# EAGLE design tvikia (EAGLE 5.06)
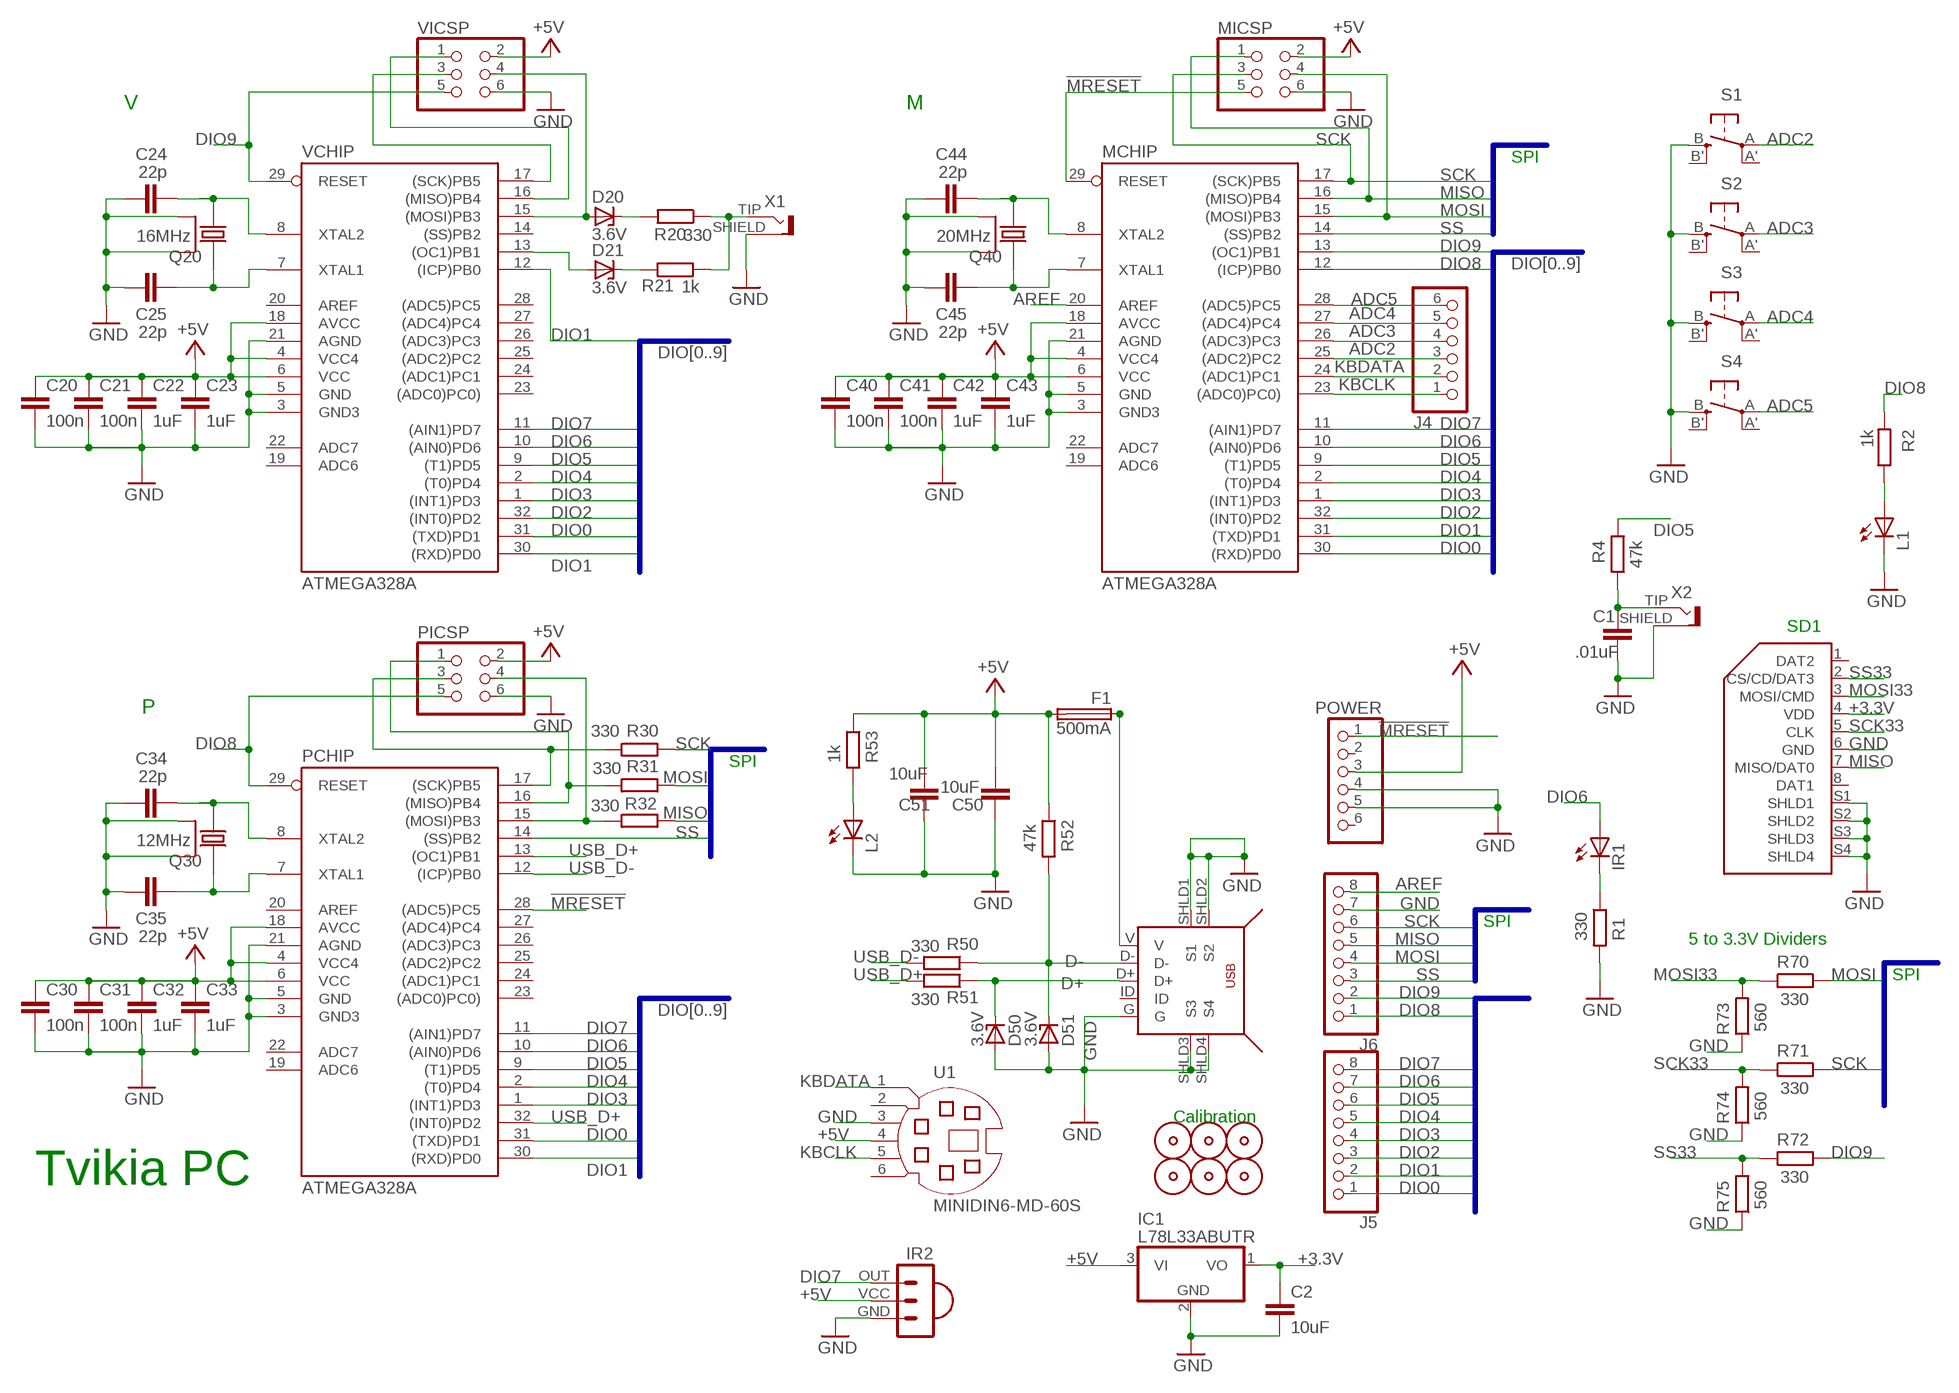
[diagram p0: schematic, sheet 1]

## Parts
C1  .01uF  C-EUC0603  [C0603]
C2  10uF  C-EUC0603  [C0603]
C20  100n  C-EUC0603  [C0603]
C21  100n  C-EUC0603  [C0603]
C22  1uF  C-EUC0603  [C0603]
C23  1uF  C-EUC0603  [C0603]
C24  22p  C-EUC0603  [C0603]
C25  22p  C-EUC0603  [C0603]
C30  100n  C-EUC0603  [C0603]
C31  100n  C-EUC0603  [C0603]
C32  1uF  C-EUC0603  [C0603]
C33  1uF  C-EUC0603  [C0603]
C34  22p  C-EUC0603  [C0603]
C35  22p  C-EUC0603  [C0603]
C40  100n  C-EUC0603  [C0603]
C41  100n  C-EUC0603  [C0603]
C42  1uF  C-EUC0603  [C0603]
C43  1uF  C-EUC0603  [C0603]
C44  22p  C-EUC0603  [C0603]
C45  22p  C-EUC0603  [C0603]
C50  10uF  C-EUC0603  [C0603]
C51  10uF  C-EUC0603  [C0603]
D20  3.6V  ZENER-DIODESOT23  [SOT23]
D21  3.6V  ZENER-DIODESOT23  [SOT23]
D50  3.6V  ZENER-DIODESOT23  [SOT23]
D51  3.6V  ZENER-DIODESOT23  [SOT23]
F1  500mA  FUSE0402  [0402]
IC1  L78L33ABUTR  [SOT89]
IR1  LED5MM  [LED5MM]
IR2  IR-RECV-TSOP323  [IR-RECV-TSOP323]
J4  PINHD-1X6-CIRC  [1X06]
J5  PINHD-1X8-CIRC  [1X08]
J6  PINHD-1X8-CIRC  [1X08]
L1  LEDCHIP-LED0603  [CHIP-LED0603]
L2  LEDCHIPLED_0603  [CHIPLED_0603]
MCHIP  ATMEGA328A  [TQFP32-08]
MICSP  PINHD-2X3  [2X03]
PCHIP  ATMEGA328A  [TQFP32-08]
PICSP  PINHD-2X3  [2X03]
POWER  PINHD-1X6-CIRC  [1X06]
Q20  16MHz  NX3225SA  [NX3225SA]
Q30  12MHz  NX3225SA  [NX3225SA]
Q40  20MHz  NX3225SA  [NX3225SA]
R1  330  R-EU_R0603  [R0603]
R2  1k  R-EU_R0603  [R0603]
R4  47k  R-EU_R0603  [R0603]
R20  330  R-EU_R0603  [R0603]
R21  1k  R-EU_R0603  [R0603]
R30  330  R-EU_R0603  [R0603]
R31  330  R-EU_R0603  [R0603]
R32  330  R-EU_R0603  [R0603]
R50  330  R-EU_R0603  [R0603]
R51  330  R-EU_R0603  [R0603]
R52  47k  R-EU_R0603  [R0603]
R53  1k  R-EU_R0603  [R0603]
R70  330  R-EU_R0603  [R0603]
R71  330  R-EU_R0603  [R0603]
R72  330  R-EU_R0603  [R0603]
R73  560  R-EU_R0603  [R0603]
R74  560  R-EU_R0603  [R0603]
R75  560  R-EU_R0603  [R0603]
S1  EVQ-Q2P02W  [EVQ-Q2P02W]
S2  EVQ-Q2P02W  [EVQ-Q2P02W]
S3  EVQ-Q2P02W  [EVQ-Q2P02W]
S4  EVQ-Q2P02W  [EVQ-Q2P02W]
SD1  MICROSD_3M_2900  [MICROSD_3M_2900]
U1  MINIDIN6-MD-60S  [MINIDIN6-MD-60S]
U$1  CALIBRATION-MARK  [CALIBRATION-MARK]
U$4  CALIBRATION-MARK  [CALIBRATION-MARK]
U$5  CALIBRATION-MARK  [CALIBRATION-MARK]
U$6  CALIBRATION-MARK  [CALIBRATION-MARK]
U$8  MICROUSB-ZX62-B-5PA  [MICROUSB-ZX62-B-5PA]
U$10  CALIBRATION-MARK  [CALIBRATION-MARK]
U$12  CALIBRATION-MARK  [CALIBRATION-MARK]
VCHIP  ATMEGA328A  [TQFP32-08]
VICSP  PINHD-2X3  [2X03]
X1  RCA-KOBICONN-161-03XX-E  [RCA-161-03XX-E]
X2  RCA-KOBICONN-161-03XX-E  [RCA-161-03XX-E]

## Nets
!MRESET: MCHIP.29(RESET) MICSP.5 PCHIP.28((ADC5)PC5) POWER.1
+3.3V: C2.1 IC1.1(VO) SD1.4(VDD)
+5V: C20.1 C21.1 C22.1 C23.1 C30.1 C31.1 C32.1 C33.1 C40.1 C41.1 C42.1 C43.1 C50.1 C51.1 F1.2 IC1.3(VI) IR2.VCC MCHIP.4(VCC4) MCHIP.6(VCC) MCHIP.18(AVCC) MICSP.2 PCHIP.4(VCC4) PCHIP.6(VCC) PCHIP.18(AVCC) PICSP.2 POWER.3 R52.1 R53.1 U1.4 VCHIP.4(VCC4) VCHIP.6(VCC) VCHIP.18(AVCC) VICSP.2
ADC2: J4.3 MCHIP.25((ADC2)PC2) S1.A(P)
ADC3: J4.4 MCHIP.26((ADC3)PC3) S2.A(P)
ADC4: J4.5 MCHIP.27((ADC4)PC4) S3.A(P)
ADC5: J4.6 MCHIP.28((ADC5)PC5) S4.A(P)
AREF: J6.8 MCHIP.20(AREF)
D+: D50.3(C) R51.1 U$8.D+
D-: D51.3(C) R50.1 R52.2 U$8.D-
DIO0: J5.1 MCHIP.30((RXD)PD0) PCHIP.31((TXD)PD1) VCHIP.31((TXD)PD1)
DIO1: J5.2 MCHIP.31((TXD)PD1) PCHIP.30((RXD)PD0) VCHIP.12((ICP)PB0) VCHIP.30((RXD)PD0)
DIO2: J5.3 MCHIP.32((INT0)PD2) VCHIP.32((INT0)PD2)
DIO3: J5.4 MCHIP.1((INT1)PD3) PCHIP.1((INT1)PD3) VCHIP.1((INT1)PD3)
DIO4: J5.5 MCHIP.2((T0)PD4) PCHIP.2((T0)PD4) VCHIP.2((T0)PD4)
DIO5: J5.6 MCHIP.9((T1)PD5) PCHIP.9((T1)PD5) R4.2 VCHIP.9((T1)PD5)
DIO6: IR1.A J5.7 MCHIP.10((AIN0)PD6) PCHIP.10((AIN0)PD6) VCHIP.10((AIN0)PD6)
DIO7: IR2.OUT J5.8 MCHIP.11((AIN1)PD7) PCHIP.11((AIN1)PD7) VCHIP.11((AIN1)PD7)
DIO8: J6.1 MCHIP.12((ICP)PB0) PCHIP.29(RESET) PICSP.5 R2.2
DIO9: J6.2 MCHIP.13((OC1)PB1) R72.2 VCHIP.29(RESET) VICSP.5
GND [power]: C1.2 C2.2 C20.2 C21.2 C22.2 C23.2 C24.1 C25.1 C30.2 C31.2 C32.2 C33.2 C34.1 C35.1 C40.2 C41.2 C42.2 C43.2 C44.1 C45.1 C50.2 C51.2 D50.1(A) D51.1(A) IC1.2(GND) IR2.GND J6.7 L1.C L2.C MCHIP.3(GND3) MCHIP.5(GND) MCHIP.21(AGND) MICSP.6 PCHIP.3(GND3) PCHIP.5(GND) PCHIP.21(AGND) PICSP.6 POWER.4 POWER.5 Q20.2(GND2) Q20.4(GND) Q30.2(GND2) Q30.4(GND) Q40.2(GND2) Q40.4(GND) R1.2 R73.1 R74.1 R75.1 S1.B(S) S2.B(S) S3.B(S) S4.B(S) SD1.6(GND) SD1.S1(SHLD1) SD1.S2(SHLD2) SD1.S3(SHLD3) SD1.S4(SHLD4) U1.3 U$8.G U$8.SHLD1(S1) U$8.SHLD2(S2) U$8.SHLD3(S3) U$8.SHLD4(S4) VCHIP.3(GND3) VCHIP.5(GND) VCHIP.21(AGND) VICSP.6 X1.SHIELD X2.SHIELD
KBCLK: J4.1 MCHIP.23((ADC0)PC0)) U1.5
KBDATA: J4.2 MCHIP.24((ADC1)PC1) U1.1
MISO: J6.5 MCHIP.16((MISO)PB4) MICSP.1 R32.1 SD1.7(MISO/DAT0)
MOSI: J6.4 MCHIP.15((MOSI)PB3) MICSP.4 R31.1 R70.2
MOSI33: R70.1 R73.2 SD1.3(MOSI/CMD)
N$2: IR1.K(C) R1.1
N$3: L2.A R53.2
N$4: C34.2 PCHIP.8(XTAL2) Q30.1
N$5: C1.1 R4.1 X2.TIP
N$8: F1.1 U$8.V
N$9: VCHIP.16((MISO)PB4) VICSP.1
N$10: C24.2 Q20.1 VCHIP.8(XTAL2)
N$11: C25.2 Q20.3 VCHIP.7(XTAL1)
N$12: D20.3(C) R20.2
N$13: D21.1(A) VCHIP.13((OC1)PB1)
N$14: D21.3(C) R21.1
N$15: R20.1 R21.2 X1.TIP
N$23: C35.2 PCHIP.7(XTAL1) Q30.3
N$24: VCHIP.17((SCK)PB5) VICSP.3
N$28: C44.2 MCHIP.8(XTAL2) Q40.1
N$29: C45.2 MCHIP.7(XTAL1) Q40.3
N$37: L1.A R2.1
PIXEL1: D20.1(A) VCHIP.15((MOSI)PB3) VICSP.4
PMISO: PCHIP.15((MOSI)PB3) PICSP.4 R32.2
PMOSI: PCHIP.16((MISO)PB4) PICSP.1 R31.2
PSCK: PCHIP.17((SCK)PB5) PICSP.3 R30.2
SCK: J6.6 MCHIP.17((SCK)PB5) MICSP.3 R30.1 R71.2
SCK33: R71.1 R74.2 SD1.5(CLK)
SS: J6.3 MCHIP.14((SS)PB2) PCHIP.14((SS)PB2)
SS33: R72.1 R75.2 SD1.2(CS/CD/DAT3)
USB_D+: PCHIP.13((OC1)PB1) PCHIP.32((INT0)PD2) R51.2
USB_D-: PCHIP.12((ICP)PB0) R50.2
Unconnected: MCHIP.19(ADC6) MCHIP.22(ADC7) PCHIP.19(ADC6) PCHIP.20(AREF) PCHIP.22(ADC7) PCHIP.23((ADC0)PC0)) PCHIP.24((ADC1)PC1) PCHIP.25((ADC2)PC2) PCHIP.26((ADC3)PC3) PCHIP.27((ADC4)PC4) POWER.2 POWER.6 S1.A'(P1) S1.B'(S1) S2.A'(P1) S2.B'(S1) S3.A'(P1) S3.B'(S1) S4.A'(P1) S4.B'(S1) SD1.1(DAT2) SD1.8(DAT1) U1.2 U1.6 U$8.ID VCHIP.14((SS)PB2) VCHIP.19(ADC6) VCHIP.20(AREF) VCHIP.22(ADC7) VCHIP.23((ADC0)PC0)) VCHIP.24((ADC1)PC1) VCHIP.25((ADC2)PC2) VCHIP.26((ADC3)PC3) VCHIP.27((ADC4)PC4) VCHIP.28((ADC5)PC5)

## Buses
DIO[0..9]
SPI:SCK,MOSI,MISO,SS

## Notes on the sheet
- V | M
- SPI
- SD1
- P
- SPI
- SPI
- 5 to 3.3V Dividers
- SPI
- Calibration
- Tvikia PC

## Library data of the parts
C1 C2 C20-C25 C30-C35 C40-C45 C50 C51 = rcl:C-EU: CAPACITOR, European symbol
D20 D21 D50 D51 = diode:ZENER-DIODE: Z-Diode
F1 = tvikia:FUSE0402
IC1 = tvikia:L78L33ABUTR: 250 mA, 16V, Low Quiescent Current LDO Regulator Source: http://ww1.microchip.com/downloads/en/DeviceDoc/22049b.pdf
IR1 L1 L2 = led:LED: LED
IR2 = tvikia:IR-RECV-TSOP323
J4 POWER = tvikia:PINHD-1X6-CIRC: PIN HEADER
J5 J6 = tvikia:PINHD-1X8-CIRC: PIN HEADER
MCHIP PCHIP VCHIP = tvikia:ATMEGA328: MICROCONTROLLER 4 Kbytes FLASH 128 bytes SRAM 256 bytes EEPROM UART 6-channel 10 bit ADC
MICSP PICSP VICSP = pinhead:PINHD-2X3: PIN HEADER
Q20 Q30 Q40 = tvikia:NX3225SA
R1 R2 R4 R20 R21 R30-R32 R50-R53 R70-R75 = rcl:R-EU_: RESISTOR, European symbol
S1-S4 = tvikia:EVQ-Q2P02W
SD1 = tvikia:MICROSD_3M_2900
U1 = tvikia:MINIDIN6-MD-60S
U$1 U$4-U$6 U$10 U$12 = tvikia:CALIBRATION-MARK: Calibration mark for board pick-n-place.
U$8 = tvikia:MICROUSB-ZX62-B-5PA
X1 X2 = tvikia:RCA-KOBICONN-161-03XX-E

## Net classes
0 default: width 0.203 mm, drill 0.305 mm, clearance 0.203 mm
1 power: width 0.356 mm, drill 0.305 mm, clearance 0.203 mm
2 gnd: width 0.356 mm, drill 0.305 mm, clearance 0.203 mm

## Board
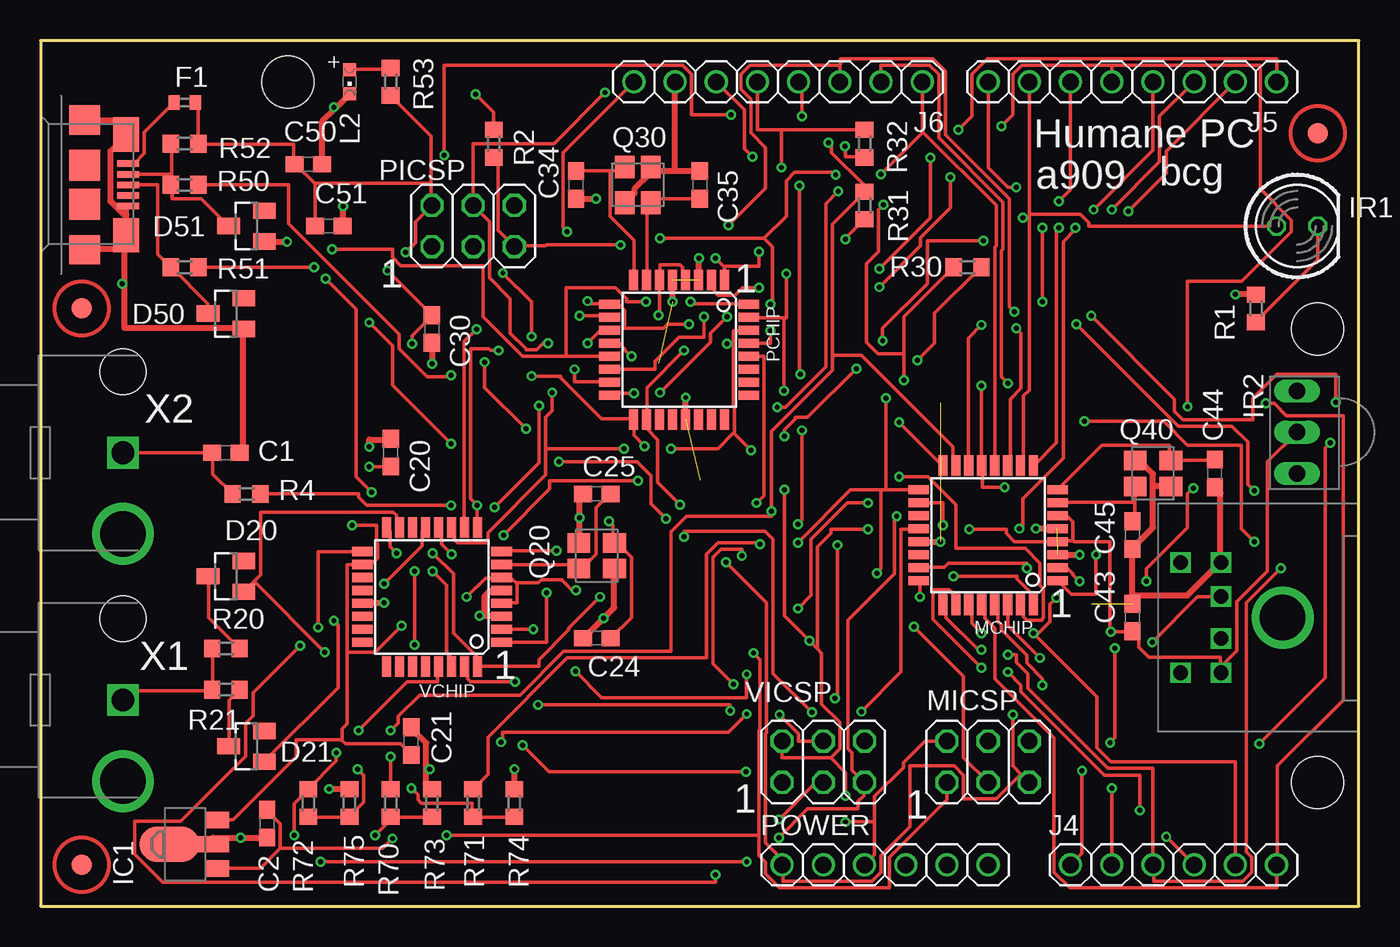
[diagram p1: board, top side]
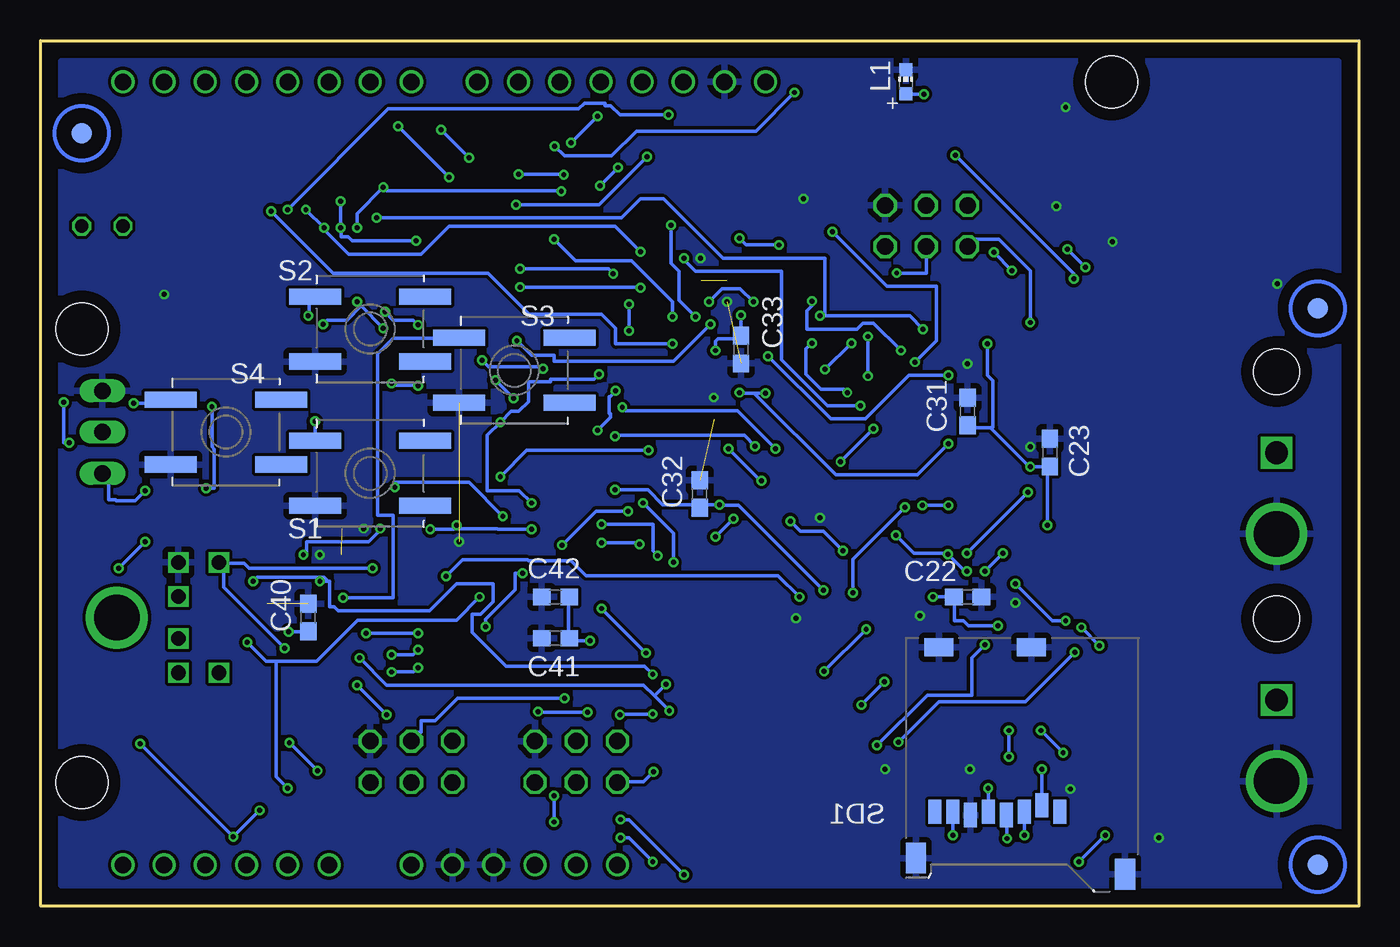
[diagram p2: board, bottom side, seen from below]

Size 81.28 x 53.34 mm. Coordinates in mm from the lower left corner, seen from the top.
Outline: 0,0 81.28,0 81.28,53.34 0,53.34 0,0
Copper layers (1*16): Top 0.035mm / dielectric 1.5mm / Bottom 0.035mm
Design rules "chung_nam_design_rules *": minimum track width 8mil, minimum drill 12mil, track to track 8mil, track to pad 8mil, pad to pad 5mil, via to via 15mil, smd to smd 5mil, copper to edge 30mil, drill to drill 30mil, minimum pad ring 7mil, minimum via ring 6mil, stop-mask expansion 3mil, vias tented up to drill 0mil, thermal gap 14mil
Holes 3.2 mm at 15.24,50.8 78.74,35.56 78.74,7.62

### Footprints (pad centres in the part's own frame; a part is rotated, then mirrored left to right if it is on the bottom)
C0603 = smd 1.1 x 1: 1 -0.85,0; 2 0.85,0
SOT23 = smd 1 x 1.4: 1 -0.95,-1.1; 2 0.95,-1.1; 3 0,1.1
0402 = smd 0.7 x 0.9: 1 -0.65,0; 2 0.65,0
SOT89 = smd 1 x 1.5: 1 -1.499,-1.981; 3 1.499,-1.981 | smd 1 x 2: 2 0,-1.727 | smd 2.2 x 3.7: 2@1 0,0.94
LED5MM = drill 0.813 octagon: A -1.27,0; K 1.27,0
IR-RECV-TSOP323 = drill 1.016 long: GND -2.54,0; OUT 2.54,0; VCC 0,0
1X06 = drill 1.016 round: 1 -6.35,0; 2 -3.81,0; 3 -1.27,0; 4 1.27,0; 5 3.81,0; 6 6.35,0
1X08 = drill 1.016 round: 1 -8.89,0; 2 -6.35,0; 3 -3.81,0; 4 -1.27,0; 5 1.27,0; 6 3.81,0; 7 6.35,0; 8 8.89,0
CHIP-LED0603 = smd 0.8 x 0.8: A 0,-0.75; C 0,0.75
CHIPLED_0603 = smd 0.8 x 0.8: A 0,-0.75; C 0,0.75
TQFP32-08 = smd 1.27 x 0.559: 1 -4.293,2.8; 2 -4.293,2; 3 -4.293,1.2; 4 -4.293,0.4; 5 -4.293,-0.4; 6 -4.293,-1.2; 7 -4.293,-2; 8 -4.293,-2.8; 17 4.293,-2.8; 18 4.293,-2; 19 4.293,-1.2; 20 4.293,-0.4; 21 4.293,0.4; 22 4.293,1.2; 23 4.293,2; 24 4.293,2.8 | smd 0.559 x 1.27: 9 -2.8,-4.293; 10 -2,-4.293; 11 -1.2,-4.293; 12 -0.4,-4.293; 13 0.4,-4.293; 14 1.2,-4.293; 15 2,-4.293; 16 2.8,-4.293; 25 2.8,4.293; 26 2,4.293; 27 1.2,4.293; 28 0.4,4.293; 29 -0.4,4.293; 30 -1.2,4.293; 31 -2,4.293; 32 -2.8,4.293
2X03 = drill 1.016 octagon: 1 -2.54,-1.27; 2 -2.54,1.27; 3 0,-1.27; 4 0,1.27; 5 2.54,-1.27; 6 2.54,1.27
NX3225SA = smd 1.4 x 1.2: 1 -1.1,-0.8; 2 1.1,-0.8; 3 1.1,0.8; 4 -1.1,0.8
R0603 = smd 1 x 1.1: 1 -0.85,0; 2 0.85,0
EVQ-Q2P02W = smd 3.2 x 1: A -3.4,2; A' 3.4,2; B -3.4,-2; B' 3.4,-2
MICROSD_3M_2900 = smd 0.8 x 1.5: 1 -9.5,10.7; 2 -8.4,10.3; 3 -7.3,10.7; 4 -6.2,10.9; 5 -5.1,10.7; 6 -4,10.9; 7 -2.9,10.7; 8 -1.8,10.7 | smd 1.24 x 1.9: S1 -13.52,14.55; S2 -0.62,13.55 | smd 1.8 x 1.1: S3 -7.75,0.55; S4 -2.05,0.55
MINIDIN6-MD-60S = drill 0.9 square: 1 -1.3,-8.5; 2 1.3,-8.5; 3 -3.4,-8.5; 4 3.4,-8.5; 5 -3.4,-11; 6 3.4,-11 | drill 2.8 round: P$7 0,-4.7
CALIBRATION-MARK = smd 1.27 x 1.27: P$1 0,0
MICROUSB-ZX62-B-5PA = smd 0.4 x 1.35: D+ 0,4.13; D- -0.65,4.13; G 1.3,4.13; ID 0.65,4.13; V -1.3,4.13 | smd 1.9 x 1.9: P$8 1.2,1.45; P$9 -1.2,1.45 | smd 2.1 x 1.6: SHLD1 -3.1,4; SHLD2 3.1,4 | smd 1.8 x 1.9: SHLD3 -4,1.45; SHLD4 4,1.45
RCA-161-03XX-E = drill 2.8 round: SHIELD 5,0 | drill 1.4 square: TIP 0,0 | hole 2.8: -5,0

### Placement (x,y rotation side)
C1  11.43,27.94 0 top
C2  13.97,5.08 270 top
C20  21.59,27.94 90 top
C21  22.86,10.16 90 top
C22  24.13,19.05 0 bottom
C23  19.05,27.94 90 bottom
C24  34.29,16.51 0 top
C25  34.29,25.4 0 top
C30  24.13,35.56 270 top
C31  24.13,30.48 90 bottom
C32  40.64,25.4 90 bottom
C33  38.1,34.29 270 bottom
C34  33.02,44.45 90 top
C35  40.64,44.45 270 top
C40  64.77,17.78 90 bottom
C41  49.53,16.51 180 bottom
C42  49.53,19.05 180 bottom
C43  67.31,17.78 90 top
C44  72.39,26.67 90 top
C45  67.31,22.86 90 top
C50  16.51,45.72 0 top
C51  17.78,41.91 0 top
D20  11.43,20.32 90 top
D21  12.7,9.84 90 top
D50  11.43,36.51 90 top
D51  12.7,41.91 90 top
F1  8.89,49.53 0 top
IC1  8.89,3.81 90 top
IR1  77.47,41.91 0 top
IR2  77.47,29.21 270 top
J4  69.85,2.54 0 top
J5  67.31,50.8 180 top
J6  45.47,50.8 180 top
L1  27.94,50.8 0 bottom
L2  19.05,50.8 180 top
MCHIP  58.42,22.86 180 top
MICSP  58.42,8.89 0 top
PCHIP  39.37,34.29 270 top
PICSP  26.67,41.91 0 top
POWER  52.07,2.54 0 top
Q20  34.29,21.59 180 top
Q30  36.83,44.45 270 top
Q40  68.58,26.67 180 top
R1  74.93,36.83 90 top
R2  27.94,46.99 270 top
R4  12.7,25.4 0 top
R20  11.43,15.88 0 top
R21  11.43,13.34 180 top
R30  57.15,39.37 0 top
R31  50.8,43.18 270 top
R32  50.8,46.99 270 top
R50  8.89,44.45 0 top
R51  8.89,39.37 0 top
R52  8.89,46.99 180 top
R53  21.59,50.8 90 top
R70  21.59,6.35 90 top
R71  26.67,6.35 90 top
R72  16.51,6.35 90 top
R73  24.13,6.35 270 top
R74  29.21,6.35 270 top
R75  19.05,6.35 270 top
S1  60.96,26.67 0 bottom
S2  60.96,35.56 0 bottom
S3  52.07,33.02 0 bottom
S4  69.85,29.21 0 bottom
SD1  27.94,16.51 180 bottom
U1  81.28,17.78 270 top
U$1  78.74,47.62 0 bottom
U$4  2.54,2.54 0 top
U$5  78.74,47.62 0 top
U$6  2.54,36.83 0 top
U$8  1.27,44.45 270 top
U$10  2.54,2.54 0 bottom
U$12  2.54,36.83 0 bottom
VCHIP  24.13,19.05 180 top
VICSP  48.26,8.89 0 top
X1  5.08,12.7 270 top
X2  5.08,27.94 270 top

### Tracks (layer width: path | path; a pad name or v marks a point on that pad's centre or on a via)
!MRESET  (via drill 0.3)
  Top 0.203: v61.77,13.61 61.77,14.02 60.81,14.99 60.81,15.44 59.23,17.02 59.23,17.32 59.03,17.53 59.03,18.34 58.83,18.54 MCHIP.29 | v59.94,11.79 59.94,8.64 60.45,8.13 | 60.45,8.13 MICSP.5 | v44.15,24.84 44.6,25.3 44.6,33.88 43.69,33.88 PCHIP.28 | v42.27,21.18 44.76,18.69 44.76,10.67 44.7,10.62 44.7,3.91 45.72,2.9 POWER.1 45.77,2.49 45.77,1.52 51.26,1.52 51.82,2.08 51.82,3.1 53.59,4.88 53.59,8.64 56.34,8.64 56.9,8.08 56.9,6.6 58.93,6.6 60.45,8.13
  Bottom 0.203: v59.94,11.79 v61.77,13.61 | v44.15,24.84 42.27,22.96 v42.27,21.18
+3.3V  (via drill 0.3)
  Top 0.203: 14.78,3.56 14.78,5.08 13.97,5.89 C2.1 | 14.78,3.56 13.56,2.34 10.87,2.34 IC1.1 | v21.69,4.17 21.08,3.56 14.78,3.56
  Bottom 0.203: v21.69,4.17 21.69,5.59 SD1.4
+5V  (via drill 0.3)
  Top 0.203: F1.2 9.7,49.38 9.7,46.99 R52.1 9.8,46.94 15.6,46.94 15.6,45.77 C50.1 15.7,45.72 16.92,44.5 | 16.92,44.5 16.92,41.91 C51.1 | v21.39,39.17 24.13,36.42 C30.1 24.08,36.32 22.91,35.15 v22.91,34.65 | v22.5,40.28 23.11,40.89 23.11,42.16 PICSP.2 24.08,43.23 24.08,44.55 | 24.08,44.55 24.08,47.45 21.59,49.94 R53.1 | 16.92,44.5 16.97,44.55 24.08,44.55 | v20.27,27.08 21.59,27.08 C20.1 | v26.26,19.05 27.43,20.22 28.4,20.22 VCHIP.6 28.5,20.22 29.01,20.22 29.36,19.86 | 29.36,19.86 29.36,18.69 28.45,18.69 VCHIP.4 | 18.54,10.26 18.8,10.01 22.2,10.01 22.86,9.35 C21.1 | 18.54,10.26 15.75,10.26 15.75,9.2 11.89,5.33 10.87,5.33 IC1.3 | 18.9,15.65 18.9,11.23 18.59,10.92 18.59,10.31 18.54,10.26 | 18.9,15.65 18.9,21.03 19.81,21.03 VCHIP.18 19.91,21.08 20.42,21.08 20.78,21.44 20.78,22.3 20.73,22.35 20.73,23.47 v19.2,23.47 | v22.25,17.27 20.62,15.65 18.9,15.65 | 63.65,22.5 62.74,22.5 MCHIP.4 62.64,22.45 60.05,22.45 59.54,22.96 59.54,23.22 v57.25,23.22 | 63.65,22.5 63.65,23.67 63.3,24.03 62.74,24.03 MCHIP.6 | v55.63,23.47 55.63,24.84 54.15,24.84 MCHIP.18 | IR2.VCC 75.64,27.38 75.64,20.62 73.76,18.75 73.76,15.75 72.8,14.78 U1.4 72.75,14.43 72.75,15.34 68.33,15.34 67.72,15.95 67.72,16.51 67.36,16.87 C43.1 67.31,16.92 v65.99,16.92 65.94,16.97 65.94,22.45 63.7,22.45 63.65,22.5 | v38.1,36.42 38.15,36.47 38.15,38.56 PCHIP.6 38.2,38.66 38.2,39.52 39.42,39.52 39.57,39.37 39.57,38.76 39.73,38.61 PCHIP.4 | v39.42,24.74 38.05,26.11 38.05,28.75 37.39,29.41 37.39,29.97 PCHIP.18 37.39,30.07 37.39,31.95 v39.67,34.24 | 47.85,15.9 48.16,15.6 48.16,12.45 49.28,11.33 49.28,9.7 48.72,9.14
  Top 0.203: 47.85,15.9 v47.4,16.36 45.87,17.88 v45.87,25.65 | 48.72,9.14 45.72,9.14 VICSP.2 | POWER.3 51.41,3.15 51.41,5.18 | 51.41,5.18 51.41,6.76 53.19,8.53 53.19,8.84 54.51,10.16 MICSP.2 | v49.63,6.81 49.63,8.23 48.72,9.14 | v49.63,5.18 51.41,5.18 | v51,23.22 48.72,23.22 48.72,22.96 47.9,22.15 47.9,15.95 47.85,15.9 | v33.02,19.46 32.77,19.46 32.16,20.07 32.16,20.12 30.89,20.12 30.68,19.91 29.41,19.91 29.36,19.86
  Bottom 0.203: v21.39,39.17 v22.5,40.28 | 22.71,29.46 23.98,29.46 24.13,29.62 C31.1 | 22.71,29.46 20.47,27.23 20.47,27.13 20.32,27.13 v20.27,27.08 19.05,27.08 C23.1 19.2,27.03 v19.2,23.47 | v26.26,19.05 C22.1 24.94,19 24.94,17.58 24.38,17.58 24.08,17.27 v22.25,17.27 | v22.91,34.65 22.91,32.72 22.55,32.36 22.55,29.52 22.66,29.52 22.71,29.46 | v57.25,23.22 55.83,23.22 55.78,23.27 55.63,23.27 v55.63,23.47 55.58,23.27 53.14,23.27 53.09,23.22 v51,23.22 | v65.99,16.92 64.77,16.92 C40.1 | v38.1,36.42 C33.1 38.15,35.05 38.25,34.95 39.52,34.95 39.67,34.8 v39.67,34.24 | C42.1 48.72,19.05 48.72,16.51 C41.1 48.62,16.46 48.51,16.36 v47.4,16.36 | v49.63,6.81 v49.63,5.18 | v45.87,25.65 43.84,25.65 42.93,24.74 40.79,24.74 40.69,24.64 C32.1 40.64,24.59 40.49,24.74 v39.42,24.74 39.37,24.69 38.25,24.69 v33.02,19.46
ADC2  (via drill 0.3)
  Top 0.203: v58.01,15.8 57.81,15.8 55.83,17.78 55.83,18.34 55.63,18.54 MCHIP.25 | v59.64,15.49 60.15,15.49 60.15,15.04 60.86,14.33 60.86,13.41 65.79,8.48 68.58,8.48 J4.3 68.63,2.49 68.63,1.52 74.12,1.52 74.68,2.08 74.68,3 74.32,3.35 74.32,18.69 v76.45,20.83 | v64.36,29.87 69.24,29.87 70.71,28.4 74.02,28.4 74.02,23.27 v74.83,22.45
  Bottom 0.203: v58.01,15.8 58.32,15.49 v59.64,15.49 | v64.36,29.87 64.36,28.7 S1.A | v76.45,20.83 v74.83,22.45
ADC3  (via drill 0.3)
  Top 0.203: v58.01,14.68 55.02,17.68 55.02,19.51 56.03,19.51 56.24,19.3 56.24,18.75 56.39,18.59 MCHIP.26 | v59.64,14.43 60.45,13.61 60.45,13.21 65.58,8.08 67.77,8.08 v67.77,5.89 | v69.39,4.27 J4.4 | v64.77,36.37 69.9,31.24 69.9,30.48 70.41,29.97 74.73,29.97 74.73,31.29 76.2,32.77 79.86,32.77 v79.86,31.04 | v79.5,28.55 79.2,28.25 79.2,14.07 v75.13,10.01
  Bottom 0.203: v58.01,14.68 58.27,14.43 v59.64,14.43 | v67.77,5.89 v69.39,4.27 v75.13,10.01 | v64.77,36.37 64.72,36.37 64.72,37.19 64.36,37.54 S2.A | v79.86,31.04 79.86,28.55 v79.5,28.55
ADC4  (via drill 0.3)
  Top 0.203: v58.01,16.82 57.4,17.42 57.4,18.39 57.25,18.54 MCHIP.27 | J4.5 73.66,8.89 65.99,8.89 65.13,9.75 65.13,12.9 v61.21,16.82 61.42,16.71 62.23,17.53 62.23,18.59 v62.64,19
  Bottom 0.203: v58.01,16.82 v61.21,16.82 | v62.64,19 59.54,19 59.54,24.08 60.5,24.08 60.5,34.04 59.54,35 55.47,35 S3.A
ADC5  (via drill 0.3)
  Top 0.203: MCHIP.28 58.06,18.54 58.22,18.39 58.22,17.73 58.83,17.12 58.83,14.02 62.48,10.36 62.48,2.08 63.45,1.12 76.2,1.12 J4.6 76.25,2.59 76.25,8.64 80.31,12.7 80.31,30.23 76.81,30.23 76.05,30.99 v75.54,30.99
  Bottom 0.203: v75.54,30.99 73.46,30.99 73.25,31.19 S4.A
AREF  (via drill 0.3)
  Top 0.203: v50.6,11.99 53.03,14.43 53.03,23.22 54.1,23.22 MCHIP.20 | v47.55,11.94 45.16,14.33 45.16,22.61 44.65,23.11 39.67,23.11 v39.67,22.76 | v38.56,23.88 37.64,24.79 37.64,26.52 36.78,27.38 v31.95,27.38 | v29.92,29.41 27.38,31.95 v27.38,33.53 | v32.46,41.55 32.21,41.81 32.21,46.43 J6.8
  Bottom 0.203: v50.6,11.99 50.55,11.94 v47.55,11.94 | v38.56,23.88 v39.67,22.76 | v29.92,29.41 v31.95,27.38 | v27.38,33.53 26.06,34.85 26.06,38.2 29.11,38.2 v32.46,41.55
D+
  Top 0.203: D50.3 10.31,36.52 10.31,37.13 8.08,39.37 R51.1 7.98,39.42 7.21,40.18 7.21,44.45 U$8.D+
D-
  Top 0.203: 8.08,45.11 8.08,46.99 R52.2 | 8.08,45.11 8.08,44.45 R50.1 8.13,44.4 8.13,43.59 9.91,43.59 11.58,41.91 D51.3 | U$8.D- 5.44,45.11 8.08,45.11
DIO0  (via drill 0.3)
  Top 0.203: v29.26,13.82 26.52,13.82 26.31,14.02 26.31,14.58 26.16,14.73 VCHIP.31 | v30.68,12.39 42.52,12.39 v42.52,12.04 | v61.62,15.29 59.64,17.27 59.64,18.54 MCHIP.30 | 45.82,36.27 45.97,36.27 v45.97,38.96 | 45.82,36.27 43.69,36.27 PCHIP.31 | v51.71,39.27 54.86,42.42 v54.86,46.13 | v56.59,47.85 57.4,48.67 57.4,51.26 58.37,52.22 76.2,52.22 J5.1 | v42.72,13.66 41.45,14.94 41.45,21.49 41.96,22 43.23,22 v43.23,21.59 | v46.69,23.52 46.94,23.77 v46.94,29.31 | v45.82,31.75 45.82,36.27
  Bottom 0.203: v29.26,13.82 v30.68,12.39 | 43.43,12.95 44.09,13.61 59.94,13.61 v61.62,15.29 | v42.52,12.04 43.43,12.95 | v45.97,38.96 46.28,39.27 v51.71,39.27 | v54.86,46.13 v56.59,47.85 | v43.23,21.59 43.54,21.89 43.54,23.52 v46.69,23.52 | v46.94,29.31 46.13,30.12 46.13,30.33 46.18,30.38 46.23,30.38 46.23,31.39 46.18,31.39 v45.82,31.75 | 43.43,12.95 v42.72,13.66
DIO1  (via drill 0.3)
  Top 0.203: v25.35,21.69 24.74,22.3 24.74,23.11 24.54,23.32 VCHIP.12 | v24.18,20.62 25.04,19.76 25.04,15.6 25.3,15.34 25.3,14.78 VCHIP.30 | 42.72,34.65 42.72,30.84 42.77,30.79 42.77,29.21 42.72,29.16 | 42.72,34.65 42.72,35.46 43.64,35.46 PCHIP.30 | 42.72,29.16 41.76,28.19 v38.86,28.19 | v36.83,26.21 31.39,26.21 31.39,25.7 v28.55,22.86 | v52.93,26.47 54.71,26.47 56.44,24.74 56.44,22.05 60.71,22.05 61.62,21.13 61.62,19.76 61.82,19.56 61.82,17.78 61.72,17.68 61.72,17.63 60.81,17.63 60.6,17.83 60.6,18.39 60.45,18.54 MCHIP.31 | 42.72,29.16 v43.79,28.09 | J5.2 69.39,46.53 69.39,45.16 v67.06,42.82 | 42.72,34.65 v42.32,34.65
  Bottom 0.203: v24.18,20.62 24.28,20.62 v25.35,21.69 25.4,21.74 27.43,21.74 v28.55,22.86 | v38.86,28.19 36.88,26.21 v36.83,26.21 | v52.93,26.47 51.31,28.09 v43.79,28.09 | v67.06,42.82 63.25,39.01 53.7,39.01 51.16,36.47 46.69,36.47 45.82,35.61 45.82,34.65 v42.32,34.65
DIO2  (via drill 0.3)
  Top 0.203: v34.49,19.05 32.56,17.12 32.56,17.02 30.73,15.19 30.73,14.78 26.98,14.78 VCHIP.32 26.98,14.88 26.98,15.29 25.45,16.82 25.45,20.47 v24.18,21.74 | v56.29,20.32 60.2,20.32 60.2,20.17 61.21,19.15 61.21,18.59 MCHIP.32 | J5.3 68.99,48.67 68.99,45.87 v66.04,42.93 | v42.57,48.77 40.13,48.77 40.13,51.26 39.57,51.82 24.89,51.82 v24.89,46.28 | v17.58,38.66 19.46,36.78 19.46,26.47 v20.42,25.5
  Bottom 0.203: v34.49,19.05 35.81,20.37 47.65,20.37 48.56,21.29 51.21,21.29 51.26,21.34 55.27,21.34 v56.29,20.32 | v66.04,42.93 59.84,49.12 48.11,49.12 47.75,49.48 46.48,49.48 46.48,49.33 46.13,49.33 45.57,48.77 v42.57,48.77 | v24.89,46.28 17.58,38.96 v17.58,38.66 | v24.18,21.74 v20.42,25.5
DIO3  (via drill 0.3)
  Top 0.203: v31.19,19.3 31.19,16.26 28.45,16.26 VCHIP.1 | v27.99,24.59 30.73,27.33 v30.73,30.84 | v41.6,39.93 42.16,39.37 | 42.16,39.37 42.16,38.61 PCHIP.1 | v65.08,21.64 65.08,19.2 63.55,19.2 62.74,20.02 MCHIP.1 | v60.35,23.27 60.55,23.47 60.55,25.09 63.04,27.58 63.04,40.95 63.8,41.71 v63.8,41.81 | v64.92,42.93 68.58,46.58 J5.4 | v44.3,40.34 44.3,39.42 42.22,39.42 42.16,39.37
  Bottom 0.203: v31.19,19.3 31.19,21.39 v27.99,24.59 | v30.73,30.84 32.77,30.84 35.61,33.68 35.61,39.12 40.89,39.12 41.6,39.83 v41.6,39.93 | v65.08,21.64 64.87,21.84 64.87,22.45 61.06,22.45 60.35,23.16 v60.35,23.27 | v64.92,42.93 v63.8,41.81 63.86,41.76 62.28,40.18 57.81,40.18 56.08,41.91 45.87,41.91 v44.3,40.34
DIO4  (via drill 0.3)
  Top 0.203: v44.3,38.1 43.28,38.1 42.82,37.64 41.76,37.64 41.55,37.85 41.55,38.41 41.4,38.56 PCHIP.2 | v51.71,38.15 54.25,40.69 54.25,41.2 56.08,43.03 v56.08,44.91 | v59.23,48.06 59.94,48.77 59.94,51.26 60.5,51.82 66.04,51.82 | 66.04,51.82 J5.5 | v30.38,17.07 28.45,17.07 VCHIP.2 | v32.97,14.48 34.59,12.85 43.54,12.85 v43.54,14.28 | v64.06,20.02 63.65,20.42 63.65,20.47 63.3,20.83 62.74,20.83 MCHIP.2 | v70.71,30.79 70.71,38.51 74.07,38.51 77.11,41.55 77.11,42.27 75.18,44.2 75.18,51.82 66.04,51.82 | v71.07,25.76 70.71,25.4 70.71,23.32 68.17,20.78 v68.17,20.02
  Bottom 0.203: v44.3,38.1 44.35,38.15 v51.71,38.15 | v59.23,48.06 v56.08,44.91 | v30.38,17.07 v32.97,14.48 | v43.54,14.28 44.04,14.78 52.58,14.78 54.66,16.87 54.66,17.98 54.15,17.98 53.39,18.75 53.39,19.86 55.63,19.86 57.3,18.19 62.94,18.19 63.2,18.44 63.45,18.44 63.45,20.02 63.6,20.02 | 63.6,20.02 v64.06,20.02 | v70.71,30.79 70.71,28.3 70.56,28.14 70.56,25.76 v71.07,25.76 | v68.17,20.02 67.92,20.27 63.8,20.27 63.6,20.07 63.6,20.02
DIO5  (via drill 0.3)
  Top 0.203: v62.79,41.81 62.64,41.66 62.64,28.55 61.27,27.18 MCHIP.9 | v62.79,43.43 63.5,44.15 J5.6 | v25.3,24.69 20.12,24.69 19.61,25.2 19.61,25.4 R4.2 | VCHIP.9 26.92,23.37 v26.92,24.69 26.52,25.09 26.52,34.34 27.64,34.34 27.74,34.24 v28.25,34.24 | v33.73,37.29 33.73,37.13 35.05,37.13 PCHIP.9 35.15,37.03 35.71,37.03 36.02,36.73 36.02,35.61 38.41,35.61 38.66,35.87 v39.98,35.87 | v58.12,41 54.66,41 54.66,38.35 51.92,35.61 v51.92,34.85
  Bottom 0.203: v62.79,43.43 v62.79,41.81 62.74,41.76 62.74,41.25 62.33,41.25 62.08,41 v58.12,41 | v25.3,24.69 v26.92,24.69 | v33.73,37.29 33.73,36.98 34.04,36.68 34.04,35.56 30.94,35.56 30.58,35.92 29.92,35.92 v28.25,34.24 | v51.92,34.85 51,33.93 49.63,33.93 49.63,33.58 42.27,33.58 v39.98,35.87
DIO6  (via drill 0.3)
  Top 0.203: v26.87,35.56 26.11,34.8 26.11,23.37 VCHIP.10 | v33.22,36.37 35.05,36.37 35.05,36.32 PCHIP.10 | 60.96,42.62 J5.7 | 60.96,42.42 60.96,42.62 | 60.96,42.42 60.96,31.8 60.6,31.45 60.6,27.33 60.45,27.18 MCHIP.10 | IR1.A 64.62,41.91 64.62,42.11 64.11,42.62 60.96,42.62 | v60.55,42.42 60.96,42.42
  Bottom 0.203: v26.87,35.56 27.69,36.37 32.92,36.37 | 32.92,36.37 v33.22,36.37 | v60.55,42.42 45.47,42.42 44.3,43.59 42.88,43.59 39.22,39.93 32.92,39.93 32.92,36.37
DIO7  (via drill 0.3)
  Top 0.203: 31.14,28.19 31.14,30.12 31.55,30.53 v31.55,31.65 | 31.14,28.19 31.14,26.57 27.58,23.01 27.58,22.4 25.7,22.4 25.5,22.61 25.5,23.16 25.35,23.32 VCHIP.11 | v33.73,34.7 34.49,35.46 35.05,35.46 PCHIP.11 | v60.15,35.61 60.45,35.31 60.45,31.9 59.79,31.24 59.79,27.33 59.64,27.18 MCHIP.11 | v61.77,41.81 v61.77,37.24 | v60.15,44.3 59.64,44.3 58.42,45.52 J5.8 | v74.83,25.6 74.42,26.01 74.42,28.6 73.46,29.57 70.16,29.57 v63.86,35.87 | v45.41,30.73 45.92,30.73 48.41,33.22 48.41,43.28 v49.17,44.04 | 31.14,28.19 v35.97,28.19
  Bottom 0.203: v31.55,31.65 31.75,31.85 33.17,31.85 34.09,32.77 34.09,34.34 v33.73,34.7 | v61.77,37.24 61.52,36.98 | 61.52,36.98 v60.15,35.61 | v61.77,41.81 61.77,42.67 v60.15,44.3 59.94,44.09 49.23,44.09 v49.17,44.04 | IR2.OUT 77.06,26.26 77.06,25.04 76.66,25.04 76.61,24.99 75.44,24.99 v74.83,25.6 | v63.86,35.87 63.6,36.12 62.38,36.12 61.52,36.98 | v35.97,28.19 38.3,30.53 45.21,30.53 v45.41,30.73
DIO8  (via drill 0.3)
  Top 0.203: R2.2 27.94,46.13 28.19,45.87 28.19,41.66 PICSP.5 29.26,40.69 31.14,40.69 31.19,40.74 v35.76,40.74 | v45.01,35.46 45.01,34.7 43.69,34.7 PCHIP.29 | v45.01,37.08 45.11,37.19 45.11,40.64 44.6,41.15 | v38.2,41.15 44.6,41.15 | 54.41,47.7 54.36,47.75 J6.1 | 54.41,47.7 58.93,43.18 58.93,40.69 58.83,40.59 58.83,27.18 MCHIP.12 | v49.02,45.06 49.02,45.21 46.48,45.21 45.97,44.7 45.97,42.52 44.6,41.15 | v51.82,45.11 54.41,47.7
  Bottom 0.203: v45.01,37.08 v45.01,35.46 | v38.2,41.15 37.8,40.74 v35.76,40.74 | v49.02,45.06 49.07,45.11 v51.82,45.11
DIO9  (via drill 0.3)
  Top 0.203: v18.24,9.45 18.24,8.94 16.51,7.21 R72.2 16.46,7.11 15.65,6.3 v15.65,4.37 | v19.61,10.82 22.61,13.82 24.49,13.82 24.49,14.73 VCHIP.29 | v58.01,32.05 58.01,27.18 MCHIP.13 58.06,27.08 58.06,25.81 v59.44,25.81 | v59.64,32.21 59.23,32.61 59.23,40.39 59.33,40.49 59.33,43.38 55.37,47.35 55.37,51.26 54.81,51.82 51.82,51.82 J6.2 | v52.78,24.03 52.63,23.88 52.63,20.47 49.78,17.63 49.78,9.7 50.04,9.45 50.04,8.38 VICSP.5 50.75,7.57 50.75,6.81 50.39,6.45 50.39,5.99 47.3,5.99 v45.52,4.22 | v17.27,2.74 v43.54,2.74
  Bottom 0.203: v18.24,9.45 v19.61,10.82 | v58.01,32.05 58.06,32.11 59.54,32.11 v59.64,32.21 | v52.78,24.03 54.86,26.11 59.38,26.11 59.44,26.06 v59.44,25.81 | v17.27,2.74 v15.65,4.37 | v43.54,2.74 45.01,4.22 v45.52,4.22
GND  (via drill 0.3)  (6 unrouted)
  Top 0.356: C1.2 12.29,27.94 12.5,28.14 12.5,35.56 D50.1 12.34,35.61 5.18,35.61 5.18,38.35 | U$8.SHLD3 2.74,48.41 5.23,48.41 5.23,47.6 U$8.SHLD1 5.18,47.4 4.32,46.53 4.32,43.43 5.13,42.62 5.28,42.62 | 5.28,42.62 5.28,41.35 U$8.SHLD2 | 5.28,42.62 5.28,43.03 5.38,43.13 U$8.G | U$8.SHLD4 2.74,40.49 5.13,40.49 5.13,41.25 U$8.SHLD2 | 5.18,38.35 5.18,40.34 U$8.SHLD2 | 68.58,25.91 69.65,25.91 Q40.4 | 68.58,25.91 68.58,26.62 67.77,27.43 67.51,27.43 Q40.2 | 68.58,25.91 68.58,23.32 67.41,22.15 C45.1 C43.2 67.46,19.15 70.71,19.15 72.64,21.08 U1.3 72.75,21.18 72.75,25.45 72.39,25.81 C44.1 | 39.12,45.31 37.64,45.31 37.64,45.52 Q30.4 37.59,45.16 36.63,44.2 36.63,43.94 36.07,43.38 Q30.2 | 39.12,45.31 40.64,45.31 C35.1 | C24.1 33.48,16.51 v34.7,17.73 35.36,18.39 35.36,20.78 Q20.4 | 18.16,49.15 17.37,48.36 17.37,45.72 C50.2 | 18.16,49.15 19.05,50.04 L2.C | IC1.2 10.62,4.22 v12.34,4.22 13.97,4.22 C2.2 | IC1.2 | 23.77,8.43 23.77,10.06 22.86,10.97 C21.2 | 23.77,8.43 23.77,7.57 24.13,7.21 R73.1 | C25.1 33.43,25.4 33.22,25.2 v33.22,23.93 33.22,22.4 Q20.2 | 27.38,17.88 28.4,17.88 VCHIP.3 | 27.38,17.88 27.38,19.1 27.69,19.41 28.4,19.41 VCHIP.5 | v17.78,7.21 19.05,7.21 R75.1 | R74.1 v29.21,8.43 | v20.27,28.3 20.27,28.75 21.59,28.75 C20.2 | C30.2 v24.13,33.43 | v18.64,43.13 18.64,41.91 C51.2 | v34.24,43.59 33.02,43.59 C34.1 | v73.66,37.69 74.93,37.69 R1.2 | v21.18,18.69 19.86,18.69 VCHIP.21 | v39.78,31.34 39.78,30.02 PCHIP.21 | v55.47,22.45 54.15,22.45 MCHIP.21 | v38.96,37.24 38.96,38.56 PCHIP.5 | v40.59,39.93 40.59,38.61 PCHIP.3 | v64.06,21.64 62.74,21.64 MCHIP.3 | v61.37,23.27 62.69,23.27 MCHIP.5 | v15.19,40.95 13.82,40.95 D51.1
  Top 0.356: v27.08,17.88 27.38,17.88 | 23.77,8.43 v23.98,8.43 | 18.16,49.15 v18.09,49.23 | 39.12,45.31 J6.7 | 5.18,38.35 v5.03,38.35
  pour Bottom: 1.27,52.07 80.01,52.07 80.01,1.27 1.27,1.27
KBCLK  (via drill 0.3)
  Top 0.203: v60.81,20.83 60.81,21.13 55.98,21.13 55.73,20.88 54.15,20.88 MCHIP.23 | J4.1 64.21,3.25 v64.21,8.33 | v65.94,10.06 66.24,10.36 v66.24,15.9
  Bottom 0.203: v60.81,20.83 68.43,20.83 68.73,21.13 70.26,21.13 U1.5 70,21.08 70,19.66 v66.24,15.9 | v64.21,8.33 v65.94,10.06
KBDATA  (via drill 0.3)
  Top 0.203: v54.2,19.05 54.2,19.96 54.15,20.02 MCHIP.24 | v68.53,16.26 71.32,19.05 72.75,19.05 U1.1 | J4.2 v66.04,7.26
  Bottom 0.203: v54.2,19.05 55.63,17.63 61.72,17.63 64.26,15.09 66.75,15.09 | 66.75,15.09 67.36,15.09 v68.53,16.26 | v66.04,7.26 66.75,7.98 66.75,15.09
MISO  (via drill 0.3)
  Top 0.203: 45.67,47.85 44.2,47.85 J6.5 | 45.67,47.85 50.8,47.85 R32.1 | v52.93,29.82 55.58,27.18 MCHIP.16 | v46.84,32.77 46.79,32.82 v46.79,44.4 | v45.67,45.52 45.67,47.85 | v25.04,4.37 44.3,4.37 | 44.3,4.37 44.3,3.1 44.7,2.69 44.7,1.98 45.57,1.12 52.32,1.12 52.32,3 55.88,6.55 MICSP.1 | v51,24.84 49.73,24.84 47.5,22.61 47.5,19.15 v46.69,18.34 | v43.94,15.6 44.35,15.19 44.35,10.87 44.3,10.82 44.3,4.37
  Bottom 0.203: v46.84,32.77 47.14,32.46 49.84,32.46 49.84,32.31 51.21,32.31 51.21,31.09 51.82,30.48 52.27,30.48 v52.93,29.82 53.75,29.01 53.75,25.6 51.77,25.6 v51,24.84 | v46.79,44.4 v45.67,45.52 | v25.04,4.37 25.04,5.79 SD1.7 | v43.94,15.6 v46.69,18.34
MOSI  (via drill 0.3)
  Top 0.203: v21.59,10.82 22.05,11.28 22.05,11.68 23.37,13.01 29.57,13.01 32.26,15.7 38.86,15.7 38.86,23.06 39.83,24.03 45.06,24.03 v45.06,24.33 45.06,29.26 48.82,33.02 48.82,33.93 | 48.82,33.93 48.82,42.01 50.8,43.99 R31.1 50.75,44.09 50.75,44.45 48.77,46.43 48.77,46.84 v48.56,47.04 | R70.2 v21.59,9.2 | MCHIP.15 56.39,27.18 56.24,27.33 56.24,28.3 50.6,33.93 48.82,33.93 | J6.4 46.94,50.6 v46.94,48.67 | v48.97,12.8 49.12,12.95 v49.12,22.25
  Bottom 0.203: v21.59,9.2 v21.59,10.82 | v48.56,47.04 v46.94,48.67 | MICSP.4 58.42,10.72 57.81,10.72 57.81,11.43 56.95,11.43 55.58,12.8 v48.97,12.8 | v49.12,22.25 47.04,24.33 v45.06,24.33
MOSI33  (via drill 0.3)
  Top 0.203: R73.2 24.13,5.49 21.59,5.49 R70.1 21.54,5.44 21.54,5.28 v20.62,4.37
  Bottom 0.203: v20.62,4.37 20.62,5.79 SD1.3
N$2
  Top 0.203: IR1.K 78.74,39.83 74.93,36.02 R1.1
N$3
  Top 0.203: L2.A 19.05,51.56 21.59,51.56 R53.2
N$4
  Top 0.203: 35.1,45.31 36.02,45.31 36.02,45.52 Q30.1 | 35.1,45.31 33.02,45.31 C34.2 | PCHIP.8 36.58,38.61 36.58,41.05 35.1,42.52 35.1,45.31
N$5
  Top 0.203: R4.1 11.84,25.4 10.62,26.62 10.62,27.94 C1.1 X2.TIP
N$8
  Top 0.203: F1.1 6.4,47.7 6.4,46.38 5.79,45.77 5.44,45.77 U$8.V
N$9  (via drill 0.3)
  Top 0.203: v21.95,21.74 21.54,22.15 21.54,23.11 21.34,23.32 VCHIP.16 | v23.06,16.1 v23.06,20.62 | v29.72,9.91 31.34,8.28 v43.48,8.28
  Bottom 0.203: v23.06,20.62 v21.95,21.74 | v23.06,16.1 23.88,15.29 23.88,13.01 26.62,13.01 v29.72,9.91 | v43.48,8.28 44.09,7.67 45.67,7.67 VICSP.1
N$10  (via drill 0.3)
  Top 0.203: C24.2 35.15,16.51 36.42,17.78 36.42,21.49 35.56,22.35 35.41,22.35 Q20.1 35.31,22.45 35.31,23.47 v35.05,23.72 | v31.8,21.89 28.45,21.89 VCHIP.8
  Bottom 0.203: v31.8,21.89 33.02,23.11 34.44,23.11 v35.05,23.72
N$11
  Top 0.203: C25.2 35.1,25.4 34.24,24.54 34.24,21.69 33.38,20.83 33.22,20.83 Q20.3 33.22,20.93 33.22,21.03 28.45,21.03 VCHIP.7
N$12
  Top 0.203: R20.2 12.24,15.9 10.36,17.78 10.36,20.32 D20.3
N$13  (via drill 0.3)
  Top 0.203: v21.18,19.86 23.52,22.2 23.52,23.11 23.72,23.32 VCHIP.13 | v18.09,17.58 18.34,17.32 18.34,13.46 13.82,8.94 D21.1
  Bottom 0.203: v21.18,19.86 18.9,17.58 v18.09,17.58
N$14
  Top 0.203: R21.1 12.24,13.31 11.63,12.7 11.63,9.86 D21.3
N$15
  Top 0.203: R20.1 10.62,15.85 10.62,13.36 R21.2 10.52,13.26 5.08,13.26 X1.TIP
N$23
  Top 0.203: C35.2 40.64,43.59 37.64,43.59 37.64,43.38 Q30.3 37.59,43.28 37.39,43.08 37.39,38.61 PCHIP.7
N$24  (via drill 0.3)
  Top 0.203: v17.12,17.17 17.12,21.84 19.81,21.84 VCHIP.17 | v16,16.05 13.11,13.16 13.11,11.73 12.65,11.28 12.65,9.25 8.64,5.23 5.79,5.23 5.79,3.2 7.52,1.47 41.6,1.47 v41.6,1.93 | v45.52,5.33 47.8,7.62 VICSP.3
  Bottom 0.203: v16,16.05 v17.12,17.17 | v41.6,1.93 45.01,5.33 v45.52,5.33
N$28
  Top 0.203: C44.2 72.39,27.48 69.7,27.48 Q40.1 69.6,27.53 69.6,28.4 65.43,28.4 62.74,25.7 MCHIP.8
N$29
  Top 0.203: 67.46,24.89 67.46,25.86 Q40.3 | 67.46,24.89 67.46,23.88 67.31,23.72 C45.2 | MCHIP.7 62.74,24.89 67.46,24.89
N$37  (via drill 0.3)
  Top 0.203: v26.82,50.04 27.94,48.92 R2.1
  Bottom 0.203: v26.82,50.04 27.94,50.04 L1.A
PIXEL1  (via drill 0.3)
  Top 0.203: 13.16,20.02 12.55,19.41 D20.1 | 13.16,20.02 13.56,20.42 13.56,24.28 21.74,24.28 21.95,24.08 21.95,23.52 22.1,23.37 VCHIP.15 | VICSP.4 46.74,10.16 46.74,10.62 v45.57,11.79 | v43.54,11.84 42.42,10.72 28.5,10.72 28.5,10.21 v28.4,10.11 | 13.16,20.02 v17.53,15.65
  Bottom 0.203: v45.57,11.79 45.52,11.84 v43.54,11.84 | v28.4,10.11 25.91,12.6 20.57,12.6 v17.53,15.65
PMISO  (via drill 0.3)
  Top 0.203: v49.58,46.84 49.63,46.79 49.63,46.18 50.8,46.18 R32.2 | v34.8,50.14 31.65,46.99 26.67,46.99 PICSP.4 27.69,42.16 27.69,38.71 28.96,37.44 28.96,35.31 29.92,34.34 29.92,34.29 30.58,34.29 30.99,34.7 v31.29,34.7 | v32.92,33.07 32.92,32.31 35.05,32.31 PCHIP.15
  Bottom 0.203: v49.58,46.84 48.97,46.23 46.08,46.23 44.55,47.75 37.19,47.75 v34.8,50.14 | v31.29,34.7 v32.92,33.07
PMOSI  (via drill 0.3)
  Top 0.203: v49.63,41.1 49.63,41.15 50.8,42.32 R31.2 | v42.32,36.32 41.3,35.31 41.3,34.75 v38.2,31.65 | v36.58,31.6 35.1,31.6 35.1,31.5 PCHIP.16 | v20.27,35.97 21.69,34.54 21.69,32.11 v25.3,28.5
  Bottom 0.203: v49.63,41.1 48.31,39.78 44.86,39.78 42.32,37.24 v42.32,36.32 | v38.2,31.65 38.15,31.6 37.24,31.6 | 37.24,31.6 v36.58,31.6 | PICSP.1 24.13,41.1 22.2,41.1 20.27,39.17 v20.27,35.97 | v25.3,28.5 27.23,26.57 32.26,26.57 37.24,31.55 37.24,31.6
PSCK  (via drill 0.3)
  Top 0.203: v54.05,33.63 55.12,34.7 55.12,36.52 57.96,39.37 R30.2 | v50.29,33.12 47.3,30.12 46.53,30.12 46.53,30.02 45.87,29.36 v45.87,28.96 | v37.24,28.35 36.58,29.01 36.58,29.97 PCHIP.17 36.47,30.02 34.59,30.02 32.05,32.56 32.05,32.66 v30.28,32.66 | v28.5,39.01 30.28,37.24 v30.28,35.1
  Bottom 0.203: v54.05,33.63 53.65,33.22 50.39,33.22 v50.29,33.12 | v45.87,28.96 45.82,29.01 37.9,29.01 v37.24,28.35 | PICSP.3 26.67,39.01 v28.5,39.01 | v30.28,32.66 v30.28,35.1
SCK  (via drill 0.3)
  Top 0.203: v44.35,22.3 44.35,22.4 41.76,22.4 41.05,21.69 41.05,15.29 32.46,15.29 27.58,10.41 27.58,8.13 26.67,7.21 R71.2 | v46.69,22.4 49.94,25.65 51.82,25.65 | 52.12,25.65 54.1,25.65 MCHIP.17 | 51.82,25.65 52.12,25.65 | v53.24,32.41 53.24,34.04 | 53.24,34.04 53.24,36.32 56.29,39.37 R30.1 | 52.12,25.65 v52.12,31.29 | MICSP.3 56.9,9.14 56.9,14.17 v53.85,17.22 | v51.56,20.52 51.82,20.78 51.82,25.65 | J6.6 43.38,49.07 43.38,46.69 v43.89,46.18 | v51.97,43.23 51.66,42.93 51.66,40.34 50.9,39.57 50.9,34.75 51.61,34.04 53.24,34.04
  Bottom 0.203: v44.35,22.3 44.45,22.4 v46.69,22.4 | v52.12,31.29 v53.24,32.41 | v53.85,17.22 53.85,17.68 52.02,19.51 52.02,20.52 v51.56,20.52 | v43.89,46.18 46.84,43.23 v51.97,43.23
SCK33  (via drill 0.3)
  Top 0.203: R74.2 29.21,5.49 26.67,5.49 R71.1 26.62,5.59 26.62,6.35 23.47,6.35 23.27,6.55 23.27,6.86 v22.86,7.26
  Bottom 0.203: v22.86,7.26 22.86,5.84 SD1.5
SS  (via drill 0.3)
  Top 0.203: v40.89,36.32 40.89,35.05 39.37,35.05 37.9,33.58 37.9,33.07 35.1,33.07 PCHIP.14 | v42.42,41.96 44.7,44.25 44.7,46.74 43.79,47.65 43.79,49.73 43.18,50.34 43.18,51.26 43.74,51.82 49.28,51.82 | 49.28,51.82 J6.3 | v58.01,35.81 57.2,35 57.2,27.18 MCHIP.14 | v60.05,36.63 59.74,36.93 59.74,43.59 55.78,47.55 55.78,51.46 55.02,52.22 49.33,52.22 49.33,51.87 49.28,51.82
  Bottom 0.203: v40.89,36.32 41.91,37.34 41.91,39.12 42.42,39.62 v42.42,41.96 | v58.01,35.81 58.32,36.12 59.54,36.12 v60.05,36.63
SS33  (via drill 0.3)
  Top 0.203: R72.1 16.51,5.49 19.05,5.49 R75.2 19.1,5.59 19.91,6.4 19.91,8.08 v19.56,8.43
  Bottom 0.203: v19.56,8.43 19.56,6.25 SD1.2
USB_D+  (via drill 0.3)
  Top 0.203: v17.98,40.49 21.69,40.49 21.69,39.98 22.2,39.47 27.28,39.47 27.28,36.32 29.72,33.88 32.41,33.88 | 32.41,33.88 35.05,33.88 PCHIP.13 | R51.2 v16.87,39.37 | v40.08,37.24 40.08,37.13 43.64,37.13 PCHIP.32 | v37.34,37.24 36.12,37.24 36.12,37.44 35.46,38.1 32.41,38.1 32.41,33.88
  Bottom 0.203: v16.87,39.37 v17.98,40.49 | v40.08,37.24 39.27,38.05 38.15,38.05 v37.34,37.24
USB_D-  (via drill 0.3)
  Top 0.203: v25.3,32.72 25.3,32.61 23.82,32.61 22.1,34.34 22.1,35.26 15.29,42.06 15.29,44.45 R50.2 | v36.42,33.88 36.02,34.29 36.02,34.34 35.71,34.65 35.1,34.65 PCHIP.12
  Bottom 0.203: v25.3,32.72 27.74,32.72 30.43,30.02 32.56,30.02 v36.42,33.88

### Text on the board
tPlace: + | Humane PC | a909 | bcg | 1 | 1 | 1 | 1 | 1 | 1
bPlace: + | S2 | S3 | S4 | S1
tNames: X2 | X1
bNames: SD1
